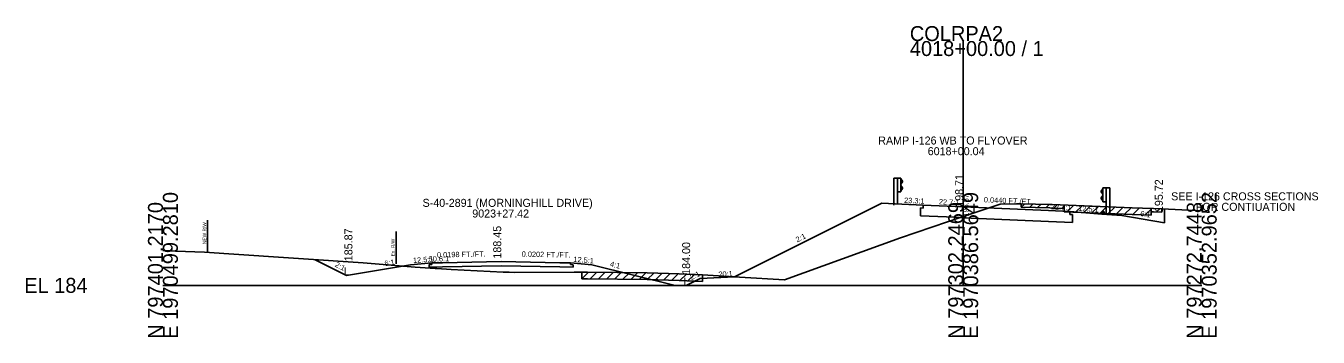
# Model space of a CAD drawing. Extents: x -26 to 1971083, y -10 to 798159.
# Drawn here: x -25.7 to 216.5, y 2490.3 to 2548.6 of the extents above; entities that cross this region are included whole.
import ezdxf

# ---------------------------------------------------------------- set-up
doc = ezdxf.new("R2010")
doc.units = 0
for name, color, linetype in [('RD_GPK_XS_Cell', 7, 'Continuous'), ('RD_XS_Base', 7, 'Continuous'), ('RD_XS_CurbTop', 7, 'Continuous'), ('RD_XS_EarthShd', 7, 'Continuous'), ('RD_XS_ExGround', 7, 'Continuous'), ('RD_XS_ExPaveRet', 7, 'Continuous'), ('RD_XS_ExRW', 7, 'Continuous'), ('RD_XS_GR', 7, 'Continuous'), ('RD_XS_Misc_Line', 7, 'Continuous'), ('RD_XS_NewRW', 7, 'Continuous'), ('RD_XS_Pave', 7, 'Continuous'), ('RD_XS_PaveShd', 7, 'Continuous'), ('RD_XS_TieSlope', 7, 'Continuous'), ('RD_XS_TX_Elev_EX', 7, 'Continuous'), ('RD_XS_TX_Elev_PR', 7, 'Continuous'), ('RD_XS_TX_Misc', 7, 'Continuous'), ('RD_XS_TX_MkPT', 7, 'Continuous'), ('RD_XS_TX_Notes', 7, 'Continuous'), ('RD_XS_TX_Profile', 7, 'Continuous'), ('RD_XS_TX_ShdSlope', 7, 'Continuous'), ('RD_XS_TX_Slope', 7, 'Continuous'), ('RD_XS_TX_Station', 7, 'Continuous')]:
    doc.layers.add(name, color=color, linetype=linetype)

msp = doc.modelspace()

# ---------------------------------------------------------------- linework, layer by layer
at = {"layer": 'RD_GPK_XS_Cell'}
for p, q in [((150, 2500), (150, 2545.74)), ((0, 2500), (150, 2500)), ((150, 2500), (194.71, 2500))]:
    msp.add_line(p, q, dxfattribs=at)
at = {"layer": 'RD_XS_Base'}
for p, q in [((141.98, 2514.5), (142.48, 2514.48)), ((141.98, 2513.02), (141.98, 2514.5)), ((142.48, 2514.48), (142.48, 2515.04)), ((148.48, 2512.74), (141.98, 2513.02)), ((148.48, 2512.74), (150, 2512.67)), ((150, 2512.67), (166, 2511.97)), ((166, 2511.97), (170.5, 2511.77)), ((170, 2513.27), (170, 2513.83)), ((170.5, 2513.25), (170, 2513.27)), ((170.5, 2511.77), (170.5, 2513.25)), ((49.9, 2503.88), (50.4, 2503.89)), ((49.9, 2503.4), (49.9, 2503.88)), ((52.4, 2503.45), (49.9, 2503.4)), ((50.4, 2503.89), (50.4, 2504.19)), ((52.4, 2503.45), (63.41, 2503.67)), ((63.41, 2503.67), (74.41, 2503.45)), ((74.41, 2503.45), (76.91, 2503.39)), ((76.41, 2503.89), (76.41, 2504.19)), ((76.91, 2503.87), (76.41, 2503.89)), ((76.91, 2503.39), (76.91, 2503.87))]:
    msp.add_line(p, q, dxfattribs=at)
at = {"layer": 'RD_XS_CurbTop'}
for p, q in [((176, 2513.35), (176.25, 2513.81)), ((176, 2513.35), (176.47, 2513.32)), ((176.47, 2513.32), (176.41, 2513.75))]:
    msp.add_line(p, q, dxfattribs=at)
msp.add_ellipse((176.32, 2513.73), major_axis=(0, -0.131), ratio=0.686, start_param=1.762783, end_param=4.036677, dxfattribs=at)
at = {"layer": 'RD_XS_EarthShd'}
for p, q in [((142.48, 2515.04), (138.48, 2515.21)), ((170, 2513.83), (176, 2513.35)), ((50.4, 2504.19), (46.4, 2503.87)), ((76.41, 2504.19), (80.42, 2503.87))]:
    msp.add_line(p, q, dxfattribs=at)
at = {"layer": 'RD_XS_ExGround'}
msp.add_lwpolyline([(0, 2506.54), (2.44, 2506.43), (7.81, 2506.21), (12.35, 2505.91), (37.53, 2504.19), (47.31, 2503.43), (51.03, 2503.14), (51.35, 2503.13), (54.05, 2503), (63.77, 2502.47), (64.89, 2502.45), (65.93, 2502.43), (77.1, 2502.45), (77.6, 2502.45), (78.54, 2502.47), (79.61, 2502.46), (90.78, 2502.33), (96.74, 2502.14), (101.14, 2502), (108.09, 2501.56), (116.48, 2501.01), (138.26, 2508.87), (150, 2512.87), (156.92, 2515.22), (160, 2515.24), (160.89, 2515.25), (166.22, 2515.12), (166.65, 2515.11), (181.66, 2514.51), (183.63, 2514.45), (185.69, 2514.38), (187.25, 2514.34), (194.71, 2513.98)], dxfattribs=at)
at = {"layer": 'RD_XS_ExPaveRet'}
for p, q in [((160.89, 2514.62), (160.89, 2515.25)), ((160.89, 2514.62), (166.22, 2514.49)), ((166.22, 2514.49), (166.65, 2514.48)), ((166.65, 2514.48), (168.95, 2514.39)), ((168.95, 2513.77), (168.95, 2515.02)), ((168.95, 2515.02), (168.95, 2514.39)), ((185.21, 2514.4), (185.21, 2513.15)), ((185.21, 2513.77), (185.21, 2514.4)), ((187.25, 2514.34), (187.25, 2513.71)), ((168.95, 2513.77), (181.66, 2513.26)), ((181.66, 2513.26), (185.21, 2513.15)), ((185.21, 2513.77), (185.69, 2513.76)), ((185.69, 2513.76), (187.25, 2513.71)), ((78.54, 2501.22), (78.54, 2502.47)), ((78.54, 2501.22), (79.61, 2501.21)), ((79.61, 2501.21), (90.78, 2501.08)), ((90.78, 2501.08), (96.74, 2500.89)), ((96.74, 2500.89), (101.14, 2500.75)), ((101.14, 2502), (101.14, 2500.75))]:
    msp.add_line(p, q, dxfattribs=at)
at = {"layer": 'RD_XS_ExRW'}
msp.add_line((43.7, 2510.06), (43.7, 2504.06), dxfattribs=at)
at = {"layer": 'RD_XS_GR'}
for p, q in [((137.66, 2520.08), (137, 2520.08)), ((137, 2520.08), (137, 2515.03)), ((138.33, 2520.08), (137.66, 2520.08)), ((137.66, 2520.08), (137.66, 2515.14)), ((138.33, 2517.52), (138.33, 2520.08)), ((138.33, 2519.92), (138.6, 2519.48)), ((138.6, 2519.37), (138.33, 2518.93)), ((138.6, 2519.48), (138.6, 2519.37)), ((138.33, 2517.52), (137.66, 2517.52)), ((138.6, 2518.23), (138.33, 2518.67)), ((138.33, 2517.68), (138.6, 2518.12)), ((138.6, 2518.12), (138.6, 2518.23)), ((176.15, 2518.07), (175.88, 2517.63)), ((175.88, 2517.63), (175.88, 2517.52)), ((175.88, 2517.52), (176.15, 2517.08)), ((175.88, 2516.37), (176.15, 2516.81)), ((176.15, 2518.23), (176.81, 2518.23)), ((176.15, 2515.66), (176.15, 2518.23)), ((176.81, 2518.23), (177.48, 2518.23)), ((176.81, 2518.23), (176.81, 2513.29)), ((177.48, 2518.23), (177.48, 2513.18)), ((175.88, 2516.26), (175.88, 2516.37)), ((176.15, 2515.82), (175.88, 2516.26)), ((176.15, 2515.66), (176.81, 2515.66))]:
    msp.add_line(p, q, dxfattribs=at)
at = {"layer": 'RD_XS_Misc_Line'}
for p, q in [((160.89, 2514.62), (161.51, 2515.23)), ((162.42, 2514.58), (163.04, 2515.19)), ((163.95, 2514.55), (164.57, 2515.16)), ((165.47, 2514.51), (166.09, 2515.12)), ((167, 2514.47), (167.61, 2515.07)), ((168.53, 2514.41), (168.95, 2514.82)), ((169.45, 2513.75), (170.67, 2514.95)), ((171.08, 2513.68), (172.3, 2514.88)), ((172.61, 2513.62), (173.83, 2514.82)), ((174.13, 2513.56), (175.36, 2514.76)), ((175.66, 2513.5), (176.89, 2514.7)), ((177.19, 2513.44), (178.42, 2514.64)), ((178.72, 2513.38), (179.94, 2514.58)), ((180.25, 2513.32), (181.47, 2514.52)), ((181.78, 2513.26), (183.01, 2514.47)), ((184.11, 2513.18), (185.34, 2514.39)), ((186.25, 2513.74), (186.87, 2514.35)), ((78.54, 2501.22), (79.8, 2502.45)), ((80.07, 2501.2), (81.33, 2502.44)), ((81.6, 2501.18), (82.86, 2502.42)), ((83.13, 2501.17), (84.39, 2502.4)), ((84.65, 2501.15), (85.91, 2502.38)), ((86.18, 2501.13), (87.44, 2502.37)), ((87.71, 2501.11), (88.97, 2502.35)), ((89.24, 2501.1), (90.5, 2502.33)), ((90.77, 2501.08), (92, 2502.29)), ((92.3, 2501.03), (93.53, 2502.24)), ((93.83, 2500.98), (95.06, 2502.19)), ((95.35, 2500.94), (96.59, 2502.15)), ((96.88, 2500.89), (98.12, 2502.1)), ((98.41, 2500.84), (99.65, 2502.05))]:
    msp.add_line(p, q, dxfattribs=at)
at = {"layer": 'RD_XS_NewRW'}
msp.add_line((8.38, 2512.18), (8.38, 2506.18), dxfattribs=at)
at = {"layer": 'RD_XS_Pave'}
for p, q in [((148.48, 2514.78), (150, 2514.71)), ((150, 2514.71), (166, 2514.01)), ((52.4, 2504.23), (63.41, 2504.45)), ((63.41, 2504.45), (74.41, 2504.23))]:
    msp.add_line(p, q, dxfattribs=at)
at = {"layer": 'RD_XS_PaveShd'}
for p, q in [((148.48, 2514.78), (142.48, 2515.04)), ((166, 2514.01), (170, 2513.83)), ((52.4, 2504.23), (50.4, 2504.19)), ((74.41, 2504.23), (76.41, 2504.19))]:
    msp.add_line(p, q, dxfattribs=at)
at = {"layer": 'RD_XS_TieSlope'}
for p, q in [((134.72, 2515.37), (107.15, 2501.6)), ((138.48, 2515.21), (134.72, 2515.37)), ((187.75, 2511.72), (187.75, 2514.31)), ((176, 2513.35), (179.75, 2513.05)), ((179.75, 2513.05), (187.75, 2511.72)), ((34.38, 2501.87), (28.51, 2504.8)), ((46.4, 2503.87), (34.38, 2501.87)), ((80.42, 2503.87), (96.01, 2499.97)), ((96.01, 2499.97), (98.07, 2499.97)), ((100.68, 2501.27), (98.07, 2499.97)), ((100.68, 2501.27), (107.15, 2501.6))]:
    msp.add_line(p, q, dxfattribs=at)

# ---------------------------------------------------------------- texts
at = {"layer": 'RD_GPK_XS_Cell'}
for s, p in [('COLRPA2', (140, 2545.74)), ('4018+00.00 / 1', (140, 2542.94)), ('EL 184', (-26, 2498.6))]:
    msp.add_text(s, height=2.8, dxfattribs=at).set_placement(p)
for s, p in [('E 1970499.2810', (2.8, 2490)), ('E 1970386.5649', (152.8, 2490)), ('E 1970352.9652', (197.51, 2490)), ('N 797401.2170', (0, 2490)), ('N 797302.2469', (150, 2490)), ('N 797272.7448', (194.71, 2490))]:
    msp.add_text(s, height=2.8, rotation=90, dxfattribs=at).set_placement(p)
at = {"layer": 'RD_XS_ExRW'}
msp.add_text('Ex. R/W ', height=0.65, rotation=90, dxfattribs=at).set_placement((43.45, 2505.44))
at = {"layer": 'RD_XS_NewRW'}
msp.add_text('NEW R/W ', height=0.65, rotation=90, dxfattribs=at).set_placement((8.12, 2507.73))
at = {"layer": 'RD_XS_TX_Elev_EX'}
msp.add_text('196.87', height=1, rotation=90, dxfattribs=at).set_placement((151, 2512.87))
at = {"layer": 'RD_XS_TX_Elev_PR'}
for s, p in [('198.71', (150, 2514.71)), (' 188.45', (63.41, 2504.45))]:
    msp.add_text(s, height=1.5, rotation=90, dxfattribs=at).set_placement(p)
at = {"layer": 'RD_XS_TX_Misc'}
for s, p in [('195.72', (187.42, 2513.72)), ('185.87', (35.52, 2504.52)), ('184.00', (98.82, 2501.97))]:
    msp.add_text(s, height=1.5, rotation=90, dxfattribs=at).set_placement(p)
at = {"layer": 'RD_XS_TX_MkPT'}
for p in [(33.88, 2501.87), (97.56, 2499.97)]:
    msp.add_text('L', height=1.5, dxfattribs=at).set_placement(p)
at = {"layer": 'RD_XS_TX_Notes'}
for s, p in [('SEE I-126 CROSS SECTIONS', (188.98, 2515.92)), ('FOR CONTIUATION', (193.61, 2513.95))]:
    msp.add_text(s, height=1.5, dxfattribs=at).set_placement(p)
at = {"layer": 'RD_XS_TX_Profile'}
msp.add_text('50.6:1', height=1, rotation=1.1332, dxfattribs=at).set_placement((49.82, 2504.43))
at = {"layer": 'RD_XS_TX_ShdSlope'}
for s, rotation, p in [('23.3:1', 357.5379, (138.91, 2515.44)), ('12.5:1', 355.4261, (171.54, 2513.96)), ('12.5:1', 4.5721, (46.9, 2504.16)), ('12.5:1', 355.4323, (76.91, 2504.4))]:
    msp.add_text(s, height=1, rotation=rotation, dxfattribs=at).set_placement(p)
at = {"layer": 'RD_XS_TX_Slope'}
for s, rotation, p in [('22.7:1', 357.4806, (145.43, 2515.17)), ('0.0440 FT./FT.', 357.4806, (153.86, 2515.55)), ('22.7:1', 357.4806, (166.43, 2514.24)), ('6:1', 350.5377, (183.13, 2513)), ('2:1', 26.5482, (118.91, 2508.03)), ('6:1', 9.4496, (41.61, 2503.58)), ('0.0198 FT./FT.', 1.1332, (51.38, 2505.21)), ('0.0202 FT./FT.', 358.8435, (67.24, 2505.37)), ('2:1', 333.444, (32.13, 2503.56)), ('4:1', 345.971, (83.72, 2503.56)), ('2:1', 26.5651, (99.06, 2500.95)), ('20:1', 2.8624, (104.14, 2501.57))]:
    msp.add_text(s, height=1, rotation=rotation, dxfattribs=at).set_placement(p)
at = {"layer": 'RD_XS_TX_Station'}
for s, p in [('RAMP I-126 WB TO FLYOVER', (134.08, 2526.37)), ('6018+00.04', (143.35, 2524.37)), ('S-40-2891 (MORNINGHILL DRIVE)', (48.67, 2514.7)), ('9023+27.42', (57.98, 2512.7))]:
    msp.add_text(s, height=1.5, dxfattribs=at).set_placement(p)

doc.saveas('drawing.dxf')
